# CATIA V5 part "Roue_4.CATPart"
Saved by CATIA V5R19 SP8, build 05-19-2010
Part number: Roue_4
Nomenclature: 70_R4
Bounding box of the stored display mesh (mm): x -28.987 to 28.987, y -28.987 to 28.987, z 0 to 15.72
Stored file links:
  C:\Users\rphgr\Desktop\0_Tapis_TC520B_vitesse\Roue_4.CATPart
  D:\Documents\1_Travail\1 - ac-limoges.fr\ac-limoges.fr\Emmanuel Maynard - STI2D_Turgot\3 - Supports\Tapis de course TC520B\Tapis de course TC520B_Ca\Roue_4.CATPart
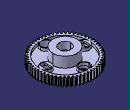
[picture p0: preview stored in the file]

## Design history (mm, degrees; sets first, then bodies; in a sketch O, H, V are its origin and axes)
Parameters
  LENGTH = 12 mm
  LargeurDenture = 8 mm
  AlphaCopie = 6.4286 deg
  Integer = 56
  Phin = 1.4644 deg
  Dn = 57.5 mm
  Phim = 1.0462 deg
  Dm = 56.5 mm
  Phil = 0.5585 deg
  Dl = 55.1557 mm
  PhiSymetrie = 1.6071 deg
  Phik = 0.109 deg
  Dk = 53.4671 mm
  Phij = 1.25 deg
  Dj = 57 mm
  Phii = 0.3061 deg
  Di = 54.3114 mm
  AlphaSymetrieCopie = 3.2143 deg
  CongePied = 0.38 mm
  PhiTete = 1.6886 deg
  PhiPrimitif = 0.854 deg
  DiamTete = 58 mm
  DiamPied = 53.5 mm
  DiamBase = 52.6228 mm
  DiamPrimitif = 56 mm
Body1 (main body)
  Sketch1 on xy-plane, origin (0, 0, 0), H (1, 0, 0), V (0, 1, 0)
    circle A1 centre (0, 0) radius 31
    circle A2 centre (0, 0) radius 6
    radius A1 = 31
    radius A2 = 6
  Pad1: profile Sketch1, direction (0, 0, 1), length 8
  Sketch2 on end face of Pad1, origin (0, 0, 8), H (1, 0, 0), V (0, 1, 0)
    circle A1 centre (0, 0) radius 12.5
    circle A2 centre (0, 0) radius 25
    radius A2 = 25
    radius A1 = 12.5
  Pocket1: profile Sketch2, direction (0, 0, -1), length 3
  Sketch3 on end face of Pad1, origin (0, 0, 8), H (1, 0, 0), V (0, 1, 0)
    projected circle E1 centre (0, 0) radius 12.5 from edge [face of Pocket1 from Sketch2.A1 | end face of Pad1]
    projected circle E2 centre (0, 0) radius 6 from edge [end face of Pad1 | face of Pad1 from Sketch1.A2]
  Pad2: profile Sketch3, direction (0, 0, 1), length 5
  Sketch4 on start face of Pad1, origin (0, 0, 0), H (1, 0, 0), V (0, -1, 0)
    circle A1 centre (0, 0) radius 25
    circle A2 centre (0, 0) radius 12.5
    reference projected circle E1 centre (0, 0) radius 25 from edge [end face of Pocket1 | face of Pocket1 from Sketch2.A2]
    radius A2 = 12.5
    coincidence: E1 A1
  Pocket2: profile Sketch4, direction (0, 0, 1), length 2.4
  Sketch5 on start face of Pad1, origin (0, 0, 0), H (1, 0, 0), V (0, -1, 0)
    projected circle E1 centre (0, 0) radius 12.5 from edge [face of Pocket2 from Sketch4.A2 | start face of Pad1]
    projected circle E2 centre (0, 0) radius 6 from edge [face of Pad2 | start face of Pad1]
  Pocket3: profile Sketch5, direction (0, 0, 1), length 1
  Sketch6 on end face of Pocket1, origin (0, 0, 5), H (1, 0, 0), V (0, 1, 0)
    circle A1 centre (0, 19.75) radius 4.75
    point P1 (0, 19.75)
    reference projected point E1 (0, 0) from axis of face of Pad2
    radius A1 = 4.75
    distance P1 E1 = 19.75
    coincidence: P1 V
  Pocket4: profile Sketch6, direction (0, 0, -1), through (limit type 3)
  CircPattern1: of Pocket4, instances 4, angular step 90 {= 360.0*1 deg/CircPattern1.AngularNumber}, axis from face of Pocket2 from Sketch4.A2
  Sketch7 on end face of Pocket3, origin (0, 0, 1), H (1, 0, 0), V (0, 1, 0)
    arc A1 centre (0, 0) radius 10.9 from (-4.58, 9.8911) to (-10.7149, 2) ccw
    arc A2 centre (0, 0) radius 8 from (-4.58, 6.5592) to (-7.746, 2) ccw
    line L1 (4.58, 9.8911) -> (4.58, 6.5592)
    line L2 (-4.58, -9.8911) -> (-4.58, -6.5592)
    line L3 (10.7149, -2) -> (7.746, -2)
    line L4 (-10.7149, 2) -> (-7.746, 2)
    point P4 (-4.58, 6.5592)
    arc A3 centre (0, 0) radius 8 from (-7.746, -2) to (-4.58, -6.5592) ccw
    point P6 (-7.746, -2)
    arc A4 centre (0, 0) radius 10.9 from (-10.7149, -2) to (-4.58, -9.8911) ccw
    point P8 (-10.7149, -2)
    line L5 (7.746, 2) -> (10.7149, 2)
    line L6 (-4.58, 6.5592) -> (-4.58, 9.8911)
    line L7 (4.58, -6.5592) -> (4.58, -9.8911)
    point P9 (7.746, 2)
    arc A5 centre (0, 0) radius 8 from (7.746, 2) to (4.58, 6.5592) ccw
    arc A6 centre (0, 0) radius 10.9 from (10.7149, 2) to (4.58, 9.8911) ccw
    line L8 (-7.746, -2) -> (-10.7149, -2)
    point P13 (4.58, -6.5592)
    arc A7 centre (0, 0) radius 8 from (4.58, -6.5592) to (7.746, -2) ccw
    arc A8 centre (0, 0) radius 10.9 from (4.58, -9.8911) to (10.7149, -2) ccw
    radius A1 = 10.9
    radius A2 = 8
    distance L6 L1 = 9.16
    distance L4 L8 = 4
    vertical: L1 V, L2 V, L6 V, L7 V
    equidistance: L1 L2 O, L3 L4 O
    horizontal: L3 H, L4 H, L5 H, L8 H
    coincidence: L2 P4, L3 P6, A2 A3, L3 P8, A1 A4, L4 L5, L2 L6, L1 L7, A3 P9, A3 A5, A4 A6, L3 L8, A3 P13, A3 A7, A4 A8
  Pocket5: profile Sketch7, direction (0, 0, 1), length 6.83
  Sketch8 on face of Pocket5, origin (0, 0, 1), H (1, 0, 0), V (0, 1, 0)
    line L1 (2.67, 11.22) -> (2.67, -11.22)
    line L2 (2.67, -11.22) -> (-2.67, -11.22)
    line L3 (-2.67, -11.22) -> (-2.67, 11.22)
    line L4 (-2.67, 11.22) -> (2.67, 11.22)
    distance L3 L1 = 5.34
    distance L2 L4 = 22.44
    vertical: L1 V, L3 V
    horizontal: L2 H, L4 H
    equidistance: L1 L3 O, L2 L4 O
  Pocket6: profile Sketch8, direction (0, 0, 1), length 5.1
  Sketch9 on end face of Pocket2, origin (0, 0, 2.4), H (1, 0, 0), V (0, -1, 0)
    circle A1 centre (0, 19.75) radius 5.45
    point P1 (0, 19.75)
    projected circle E1 centre (0, 19.75) radius 4.75 from edge [end face of Pocket2 | face of CircPattern1]
    distance E1 A1 = 0.7
    coincidence: P1 V
    concentricity: E1 A1
  Pad3: profile Sketch9, direction (0, 0, -1), up to start face of Pad1, opposite side up to end face of Pad1
  Sketch10 on face of Pad1, origin (0, 0, 0), H (1, 0, 0), V (0, -1, 0)
    point P1 (0, 19.75)
    line L1 (4.9173, 17.4) -> (-4.9173, 17.4)
    line L2 (-4.9173, 22.1) -> (4.9173, 22.1)
    arc A1 centre (0, 19.75) radius 5.45 from (4.9173, 22.1) to (-4.9173, 22.1) ccw
    reference projected circle E1 centre (0, 19.75) radius 5.45 from edge [end face of Pad3 | face of Pad3 from Sketch9.A1]
    point P5 (-4.9173, 17.4)
    arc A2 centre (0, 19.75) radius 5.45 from (-4.9173, 17.4) to (4.9173, 17.4) ccw
    distance L2 L1 = 4.7
    horizontal: L1 H, L2 H
    equidistance: L1 L2 P1
    coincidence: A1 E1, A1 P5, A1 A2
  Pad4: profile Sketch10, direction (0, 0, 1), length 1.6
  Mirror1: of Pad3, Pad4, about zx-plane
  Sketch11 on end face of Pocket1, origin (0, 0, 5), H (1, 0, 0), V (0, 1, 0)
    circle A1 centre (19.75, 0) radius 4.75
    circle A2 centre (19.75, 0) radius 5.35
    reference projected circle E1 centre (19.75, 0) radius 4.75 from edge [end face of Pocket1 | face of CircPattern1]
    distance A2 A1 = 0.6
    coincidence: A1 E1
  Pad5: profile Sketch11, direction (0, 0, 1), up to face of Mirror1, opposite side up to face of Pad1
  Sketch12 on start face of Pad5, origin (0, 0, 8), H (1, 0, 0), V (0, -1, 0)
    arc A1 centre (19.75, 0) radius 5.35 from (22.1, -4.8062) to (22.1, 4.8062) ccw
    point P1 (19.75, 0)
    line L1 (22.1, 4.8062) -> (22.1, -4.8062)
    line L2 (17.4, -4.8062) -> (17.4, 4.8062)
    reference projected circle E1 centre (19.75, 0) radius 5.35 from edge [face of Pad5 from Sketch11.A2 | end face of Pad5]
    point P5 (17.4, 4.8062)
    arc A2 centre (19.75, 0) radius 5.35 from (17.4, 4.8062) to (17.4, -4.8062) ccw
    distance L1 L2 = 4.7
    vertical: L1 V, L2 V
    equidistance: L1 L2 P1
    coincidence: A1 E1, A1 P5, A1 A2
  Pad6: profile Sketch12, direction (0, 0, -1), length 1.6
  Mirror2: of Pad5, Pad6, about yz-plane
  Plane1: type Offset, RefPlane end face of Pocket2, Offset 2, reversed
  Sketch13 on end face of Pocket3, origin (0, 0, 1), H (1, 0, 0), V (0, 1, 0)
    line L1 (23.0748, 9.5579) -> (11.0925, 4.5946)
    angle L1 H = 22.5
    coincidence: L1 O
  Stiffener1: ThicknessValue 1, ExtendedProfile Sketch13, ThicknessTop 0
  CircPattern2: of Stiffener1, instances 8, angular step 45 {= 360.0*1 deg/CircPattern2.AngularNumber}, axis from face of Pad2
  Body2
    Sketch14 on xy-plane, origin (0, 0, 0), H (1, 0, 0), V (0, 1, 0)
      construction circle A1 centre (0, 0) radius 28
      construction circle A2 centre (0, 0) radius 26.3114
      construction circle A3 centre (0, 0) radius 26.75
      construction circle A4 centre (0, 0) radius 29
      point P1 (26.3114, 0)
      construction line L1 (26.3114, 0) -> (0, 0)
      point P2 (27.9969, 0.4173)
      construction line L2 (27.9969, 0.4173) -> (0, 0)
      point P3 (28.9874, 0.8546)
      construction line L3 (28.9874, 0.8546) -> (0, 0)
      construction line L4 (26.3114, 0) -> (26.3114, 3.9367)
      point P4 (26.3114, 0)
      point P6 (24.6259, 0.4173)
      construction line L5 (28.9874, 0.8546) -> (27.9969, 0.4173)
      point P7 (28.4921, 0.6359)
      point P8 (24.1306, 0.6359)
      spline S1 through (24.1306, 0.6359) (24.6259, 0.4173) (26.3114, 0) (26.7335, 0.0509) (27.1553, 0.1451) (27.5765, 0.2688) (27.9969, 0.4173) (28.2453, 0.5158) (28.4932, 0.6217) (28.7406, 0.7347) (28.9874, 0.8546)
      construction line L6 (0, 0) -> (5.2695, 0.2265)
      spline S2 through (24.0962, 1.4369) (24.5709, 1.6972) (26.2144, 2.2576) (26.6393, 2.2431) (27.0676, 2.1855) (27.4979, 2.0983) (27.9294, 1.9864) (28.1854, 1.9096) (28.4415, 1.8254) (28.6977, 1.734) (28.9538, 1.6358)
      arc A5 centre (27.1288, -0.2534) radius 0.38 from (27.0395, 0.1159) to (26.7488, -0.2499) ccw
      point P11 (26.7488, -0.2499)
      arc A6 centre (0, 0) radius 29 from (28.9874, 0.8546) to (28.9538, 1.6358) ccw
      point P13 (28.9538, 1.6358)
      arc A7 centre (27.007, 2.5802) radius 0.38 from (26.6287, 2.5441) to (26.9497, 2.2046) ccw
      point P15 (26.6287, 2.5441)
      construction line L7 (0, 0) -> (4.2622, 0.4236)
      construction line L8 (0, 0) -> (5.1254, -0.0674)
      point P19 (26.6189, 2.6454)
      arc A8 centre (0, 0) radius 26.75 from (26.6287, 2.5441) to (26.6189, 2.6454) ccw
      point P20 (26.7477, -0.3516)
      arc A9 centre (0, 0) radius 26.75 from (26.7477, -0.3516) to (26.7488, -0.2499) ccw
      line L9 (26.6189, 2.6454) -> (0, 0)
      line L10 (26.7477, -0.3516) -> (0, 0)
      construction circle A10 centre (0, 0) radius 27.1557
      construction line L11 (0, 0) -> (2.5698, 0.0137)
      point P22 (27.1553, 0.1451)
      construction circle A11 centre (0, 0) radius 28.5
      construction line L12 (0, 0) -> (4.0181, 0.0877)
      point P24 (28.4932, 0.6217)
      point P25 (28.4932, 0.6217)
      point P26 (28.4415, 1.8254)
      point P27 (27.0676, 2.1855)
      construction circle A12 centre (0, 0) radius 26.7335
      construction line L13 (0, 0) -> (48.2618, 0.0918)
      point P29 (26.6393, 2.2431)
      construction line L14 (0, 0) -> (63.9195, 2.7473)
      point P31 (26.7335, 0.0509)
      construction circle A13 centre (0, 0) radius 27.5778
      construction line L15 (0, 0) -> (57.3607, 0.5591)
      point P33 (27.5765, 0.2688)
      point P34 (27.4979, 2.0983)
      construction circle A14 centre (0, 0) radius 28.25
      construction line L16 (0, 0) -> (65.6998, 1.1998)
      point P36 (28.2453, 0.5158)
      point P37 (28.1854, 1.9096)
      construction circle A15 centre (0, 0) radius 28.75
      axis line L17 (0, 0) -> (59.3316, 1.5168)
      point P39 (28.6977, 1.734)
      point P40 (28.7406, 0.7347)
      point P42 (24.1306, 0.6359)
      point P43 (24.6259, 0.4173)
      point P44 (26.3114, 0)
      point P45 (27.9969, 0.4173)
      point P46 (28.9874, 0.8546)
      point P47 (28.9538, 1.6358)
      point P48 (24.0962, 1.4369)
      point P49 (27.9294, 1.9864)
      point P50 (26.2144, 2.2576)
      point P51 (24.5709, 1.6972)
      point P52 (27.1553, 0.1451)
      point P53 (28.4932, 0.6217)
      point P54 (27.0676, 2.1855)
      point P55 (28.4415, 1.8254)
      point P56 (26.7335, 0.0509)
      point P57 (26.6393, 2.2431)
      point P58 (27.5765, 0.2688)
      point P59 (27.4979, 2.0983)
      point P60 (28.2453, 0.5158)
      point P61 (28.1854, 1.9096)
      point P62 (28.7406, 0.7347)
      point P63 (28.6977, 1.734)
      radius A1 = 28 {= DiamPrimitif /2}
      radius A2 = 26.3114 {= DiamBase /2}
      radius A3 = 26.75 {= DiamPied /2}
      radius A4 = 29 {= DiamTete /2}
      angle L2 L1 = 0.854 {= PhiPrimitif}
      angle L3 L1 = 1.6886 {= PhiTete}
      angle L4 L1 = 90
      radius A5 = 0.38 {= CongePied}
      radius A7 = 0.38 {= CongePied}
      angle L7 L6 = 3.2143 {= AlphaSymetrieCopie}
      angle L2 L6 = 1.6071 {= PhiSymetrie}
      radius A10 = 27.1557 {= Di /2}
      angle L11 L1 = 0.3061 {= Phii}
      radius A11 = 28.5 {= Dj /2}
      angle L12 L1 = 1.25 {= Phij}
      radius A12 = 26.7335 {= Dk/2}
      angle L13 L1 = 0.109 {= Phik}
      angle L14 L2 = 1.6071 {= PhiSymetrie}
      radius A13 = 27.5778 {= Dl /2}
      angle L15 L1 = 0.5585 {= Phil}
      radius A14 = 28.25 {= Dm /2}
      angle L16 L1 = 1.0462 {= Phim}
      radius A15 = 28.75 {= Dn/2}
      angle L17 L1 = 1.4644 {= Phin}
      coincidence: P1 A2, P1 H, P2 A1, P3 A4, P4 A2, P7 L5, P42 P8, P43 P6, P44 P1, P45 L5, P45 L2, P46 L5, P46 L3, P11 A3, P47 P13, P15 A3, P19 L7, P19 A3, P20 L8, P20 A3, P3 P46, P22 L11, P22 A10, P52 P22, P24 L12, P24 A11, P53 P24, P25 P53, P54 P27, P55 P26, P31 L13, P31 A12, P56 P31, P57 P29, P33 L15, P33 A13, P58 P33, P59 P34, P36 L16, P36 A14, P60 P36, P61 P37, P40 L17, P40 A15, P62 P40, P63 P39, O L9, O L10
      horizontal: L1 H
      tangency: L4 A2, A5 A3, A5 S1, A7 A3, A7 S2, A8 A5, A9 A5
      symmetry: P6 P2 L4, P8 P7 L4, P46 P47 L6, P42 P48 L6, P45 P49 L6, P44 P50 L6, P43 P51 L6, L8 L7 L6, P26 P25 L6, P27 P22 L6, P29 P31 L14, P34 P33 L14, P37 P36 L14, P39 P40 L14
      midpoint: P7 L5
      parallelism: L9 L7, L10 L8
      concentricity: A10 A2, A11 A1
    Pad7: profile Sketch14, direction (0, 0, 1), length 8 {= LargeurDenture}
    CircPattern3 "Roue Dentée": of Pad7, instances 56 {= Integer}, angular step 6.4286 {= AlphaCopie}, axis from Z axis
    Body3
      Sketch15 on xy-plane, origin (0, 0, 0), H (1, 0, 0), V (0, 1, 0)
        circle A1 centre (0, 0) radius 6
        radius A1 = 6 {= LENGTH /2}
      Pad8: profile Sketch15, direction (0, 0, 1), length 16 {= 2*LargeurDenture}
    Remove1: tool Body3
  Intersect1: tool Body2
  Sketch16 on face of CircPattern3, origin (0, 0, 8), H (1, 0, 0), V (0, 1, 0)
    projected circle E1 centre (0, 0) radius 12.5 from edge [face of Pad2 | face of CircPattern3]
    projected circle E2 centre (0, 0) radius 6 from edge [face of CircPattern3 | face of Pad8]
  Pad9: profile Sketch16, direction (0, 0, 1), length 7.72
